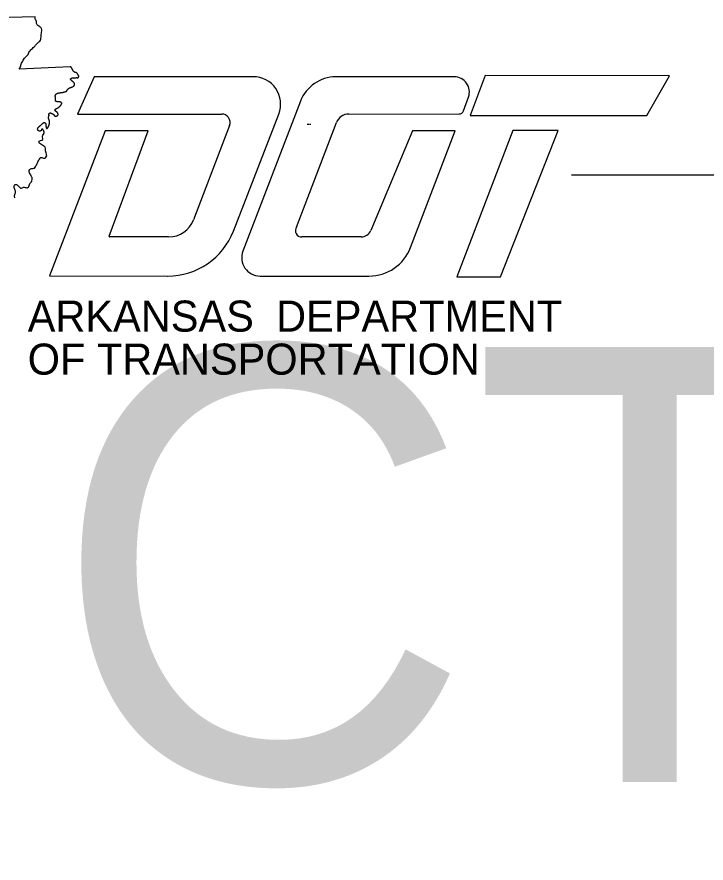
# Model space of a CAD drawing. Extents: x 840176 to 859715, y 1589036 to 1600368.
# Drawn here: x 848478 to 848941, y 1598648 to 1599216 of the extents above; entities that cross this region are included whole.
import ezdxf

# ---------------------------------------------------------------- set-up
doc = ezdxf.new("R2010")
doc.units = 0
for name, color, linetype in [('Default', 7, 'Continuous'), ('DSN_DRFT_Border', 7, 'Continuous'), ('SHET_Border-Lines', 7, 'Continuous')]:
    doc.layers.add(name, color=color, linetype=linetype)

msp = doc.modelspace()

# ---------------------------------------------------------------- linework, layer by layer
at = {"layer": 'Default'}
msp.add_line((848850.24, 1599109.73), (849966.97, 1599109.73), dxfattribs=at)
at = {"layer": 'DSN_DRFT_Border'}
for p, q in [((848672.92, 1599143.76), (848674, 1599143.76)), ((848674.34, 1599143.76), (848675.42, 1599143.76))]:
    msp.add_line(p, q, dxfattribs=at)
msp.add_lwpolyline([(848674.14, 1599143.71), (848674.14, 1599143.72), (848674.13, 1599143.73), (848674.13, 1599143.78), (848674.13, 1599143.81), (848674.23, 1599143.81), (848674.23, 1599143.8), (848674.23, 1599143.8), (848674.24, 1599143.8), (848674.21, 1599143.74), (848674.21, 1599143.71)], close=True, dxfattribs=at)
at = {"layer": 'SHET_Border-Lines'}
for p, q in [((848513.7, 1599182.3), (848479.52, 1599180.58)), ((848529.83, 1599175.52), (848518.6, 1599150.52)), ((848636.63, 1599175.57), (848529.83, 1599175.52)), ((848771.6, 1599175.51), (848692.13, 1599175.48)), ((848792.38, 1599176.27), (848782.17, 1599149.5)), ((848916.08, 1599176.05), (848792.38, 1599176.27)), ((848900.8, 1599149.5), (848916.08, 1599176.05)), ((848777.76, 1599152.59), (848781.14, 1599161.88)), ((848668.35, 1599159.13), (848629.76, 1599058.46)), ((848518.6, 1599150.52), (848615.49, 1599150.51)), ((848623.35, 1599071.94), (848653.81, 1599150.5)), ((848700.8, 1599150.51), (848774.82, 1599150.53)), ((848782.17, 1599149.5), (848900.8, 1599149.5)), ((848665.67, 1599074.61), (848692.5, 1599144.8)), ((848566.11, 1599139.27), (848537.36, 1599139.28)), ((848539.88, 1599068.57), (848566.11, 1599139.27)), ((848620.75, 1599142.89), (848596.65, 1599079.57)), ((848743.56, 1599139.3), (848715.57, 1599072.3)), ((848742.25, 1599060.88), (848772.29, 1599139.22)), ((848772.29, 1599139.22), (848743.56, 1599139.3)), ((848811.01, 1599139.45), (848773.36, 1599041.27)), ((848802.56, 1599041.27), (848841.41, 1599139.45)), ((848841.41, 1599139.45), (848811.01, 1599139.45)), ((848579.87, 1599068), (848540.28, 1599067.99)), ((848709.1, 1599067.99), (848669.26, 1599067.95)), ((848641.26, 1599041.72), (848714.34, 1599041.7)), ((848773.36, 1599041.27), (848802.56, 1599041.27))]:
    msp.add_line(p, q, dxfattribs=at)
for points in [[(848490.35, 1599215.71), (848455.4, 1599214.89), (848380.06, 1599213.74), (848316.15, 1599213.61), (848243.39, 1599213.66)], [(848537.36, 1599139.28), (848499.85, 1599041.81), (848579.21, 1599041.74)]]:
    msp.add_lwpolyline(points, dxfattribs=at)
for centre, radius, start, end in [((848636.64, 1599157.15), 18.41, 338.81, 90.0244), ((848692.14, 1599150.01), 25.47, 90.0159, 159.0252), ((848771.61, 1599165.36), 10.15, 339.9797, 90.0159), ((848615.49, 1599144.89), 5.63, 339.1692, 89.9954), ((848700.8, 1599141.63), 8.88, 90.0183, 159.0781), ((848774.82, 1599153.67), 3.13, 270.0183, 339.9797), ((848579.87, 1599085.95), 17.95, 270.0081, 339.1692), ((848579.25, 1599089.03), 47.3, 269.9471, 338.81), ((848669.24, 1599072.24), 4.29, 146.4856, 270.228), ((848709.09, 1599075.01), 7.02, 270.0618, 337.3322), ((848540.28, 1599068.42), 0.424, 159.6445, 270.0081), ((848641.26, 1599054.05), 12.32, 159.0252, 269.9823), ((848714.35, 1599071.58), 29.88, 269.9823, 339.0187)]:
    msp.add_arc(centre, radius, start, end, dxfattribs=at)
for points in [[(848479.52, 1599180.58), (848480.73, 1599183.32), (848480.98, 1599184.67), (848482.01, 1599186.03), (848482.54, 1599187.28), (848483.64, 1599188.49), (848484.46, 1599189.38), (848485.46, 1599190.38), (848485.95, 1599191.76), (848486.87, 1599193.01), (848487.81, 1599194.01), (848488.96, 1599195.14), (848490.17, 1599196.21), (848490.83, 1599197.24), (848491.78, 1599198.18), (848492.8, 1599198.98), (848493.9, 1599200.1), (848494.16, 1599201.51), (848494.34, 1599203.04), (848494.41, 1599204.78), (848494.77, 1599206.34), (848494.52, 1599207.88), (848493.36, 1599209.21), (848492.06, 1599210), (848491.29, 1599210.82), (848491.19, 1599212.71), (848490.58, 1599213.74), (848490.35, 1599215.71)], [(848488.7, 1599114.01), (848489.78, 1599114.22), (848490.78, 1599115.57), (848491.27, 1599116.73), (848491.78, 1599117.8), (848492.44, 1599119.08), (848493.11, 1599120.31), (848494.06, 1599121.23), (848495.23, 1599121.15), (848496.26, 1599120.82), (848497.2, 1599121.1), (848497.99, 1599122.43), (848497.82, 1599123.58), (848497.38, 1599125.17), (848497.15, 1599126.37), (848496.89, 1599128.19), (848496.05, 1599128.98), (848494.69, 1599129.72), (848493.36, 1599130.74), (848492.62, 1599131.79), (848493.9, 1599132.71), (848495.33, 1599133.48), (848495.18, 1599134.89), (848495.46, 1599136.27), (848496.26, 1599137.68), (848496.08, 1599138.96)], [(848476.5, 1599094.34), (848476.66, 1599096.44), (848477.07, 1599097.67), (848476.63, 1599099.74), (848476.2, 1599101.27), (848476.38, 1599102.76), (848477.32, 1599103.24), (848478.24, 1599102.94), (848479.04, 1599102.12), (848480.01, 1599101.07), (848480.96, 1599100.74), (848481.93, 1599101.25), (848482.93, 1599101.32), (848484.08, 1599101.12), (848485.15, 1599101.02), (848485.71, 1599101.38), (848486.28, 1599102.45), (848486.66, 1599103.88), (848487.45, 1599104.57), (848488.07, 1599105.7), (848488.32, 1599107.21), (848487.86, 1599108.44), (848487.22, 1599109.82), (848486.41, 1599110.97), (848486.28, 1599112.63), (848487.12, 1599113.63), (848488.58, 1599113.99), (848488.7, 1599114.01)]]:
    msp.add_spline(points, degree=3, dxfattribs=at)
for points in [[(848516.17, 1599174.7), (848516.28, 1599174.69), (848516.39, 1599174.68), (848516.49, 1599174.7), (848516.72, 1599174.73), (848516.95, 1599174.77), (848517.18, 1599174.81), (848517.41, 1599174.85), (848517.64, 1599174.89), (848517.87, 1599174.93), (848517.93, 1599174.94), (848517.98, 1599174.94), (848518.03, 1599174.94), (848518.09, 1599174.94), (848518.14, 1599174.94), (848518.19, 1599174.93), (848518.3, 1599174.93), (848518.41, 1599174.91), (848518.51, 1599174.9), (848518.62, 1599174.9), (848518.73, 1599174.9), (848518.83, 1599174.91), (848518.95, 1599174.93), (848519.05, 1599174.97), (848519.15, 1599175.03), (848519.17, 1599175.04), (848519.19, 1599175.06), (848519.21, 1599175.07), (848519.23, 1599175.09), (848519.25, 1599175.1), (848519.27, 1599175.12), (848519.3, 1599175.15), (848519.33, 1599175.19), (848519.35, 1599175.23), (848519.41, 1599175.3), (848519.44, 1599175.39), (848519.47, 1599175.48), (848519.49, 1599175.57), (848519.5, 1599175.66), (848519.5, 1599175.75), (848519.5, 1599175.83), (848519.49, 1599175.92), (848519.46, 1599176), (848519.33, 1599176.42), (848519.13, 1599176.78), (848518.9, 1599177.15), (848518.65, 1599177.54), (848518.39, 1599177.89), (848518.03, 1599178.18), (848517.94, 1599178.24), (848517.86, 1599178.29), (848517.76, 1599178.31), (848517.66, 1599178.34), (848517.56, 1599178.36), (848517.46, 1599178.38), (848517.36, 1599178.41), (848517.26, 1599178.42), (848517.16, 1599178.45), (848517.06, 1599178.47), (848516.97, 1599178.51), (848516.88, 1599178.56), (848516.51, 1599178.76), (848516.19, 1599179), (848515.93, 1599179.33), (848515.85, 1599179.43), (848515.78, 1599179.54), (848515.72, 1599179.65), (848515.67, 1599179.77), (848515.61, 1599179.88), (848515.56, 1599180), (848515.51, 1599180.11), (848515.46, 1599180.23), (848515.4, 1599180.35), (848515.35, 1599180.46), (848515.28, 1599180.57), (848515.21, 1599180.68), (848515.16, 1599180.77), (848515.11, 1599180.85), (848515.06, 1599180.93), (848515, 1599181.01), (848514.95, 1599181.1), (848514.9, 1599181.18), (848514.8, 1599181.35), (848514.69, 1599181.52), (848514.57, 1599181.69), (848514.47, 1599181.84), (848514.35, 1599181.97), (848514.19, 1599182.09), (848514.04, 1599182.2), (848513.88, 1599182.27), (848513.7, 1599182.3)], [(848512.12, 1599167.1), (848512.14, 1599167.13), (848512.17, 1599167.15), (848512.19, 1599167.18), (848512.28, 1599167.28), (848512.38, 1599167.38), (848512.48, 1599167.48), (848512.57, 1599167.58), (848512.68, 1599167.67), (848512.79, 1599167.75), (848512.9, 1599167.84), (848513.01, 1599167.91), (848513.14, 1599167.97), (848513.26, 1599168.02), (848513.37, 1599168.07), (848513.49, 1599168.11), (848513.61, 1599168.16), (848513.73, 1599168.2), (848513.85, 1599168.24), (848513.97, 1599168.28), (848514.1, 1599168.31), (848514.22, 1599168.35), (848514.34, 1599168.39), (848514.45, 1599168.44), (848514.57, 1599168.48), (848514.81, 1599168.57), (848515.05, 1599168.66), (848515.28, 1599168.76), (848515.53, 1599168.86), (848515.75, 1599168.98), (848515.98, 1599169.12), (848516.09, 1599169.19), (848516.17, 1599169.27), (848516.26, 1599169.36), (848516.35, 1599169.45), (848516.41, 1599169.54), (848516.48, 1599169.65), (848516.59, 1599169.86), (848516.68, 1599170.07), (848516.72, 1599170.3), (848516.74, 1599170.4), (848516.75, 1599170.5), (848516.74, 1599170.6), (848516.73, 1599170.71), (848516.71, 1599170.82), (848516.68, 1599170.93), (848516.65, 1599171.04), (848516.61, 1599171.14), (848516.56, 1599171.24), (848516.5, 1599171.34), (848516.44, 1599171.44), (848516.36, 1599171.52), (848516.27, 1599171.64), (848516.16, 1599171.74), (848516.05, 1599171.84), (848515.94, 1599171.93), (848515.83, 1599172.02), (848515.72, 1599172.1), (848515.61, 1599172.19), (848515.49, 1599172.27), (848515.38, 1599172.36), (848515.27, 1599172.45), (848515.17, 1599172.55), (848515.06, 1599172.65), (848514.85, 1599172.84), (848514.65, 1599173.04), (848514.45, 1599173.25), (848514.35, 1599173.34), (848514.27, 1599173.44), (848514.2, 1599173.55), (848514.13, 1599173.65), (848514.09, 1599173.74), (848514.06, 1599173.85), (848514.06, 1599173.87), (848514.06, 1599173.9), (848514.06, 1599173.92), (848514.06, 1599173.94), (848514.06, 1599173.96), (848514.07, 1599173.99), (848514.08, 1599174.03), (848514.11, 1599174.08), (848514.14, 1599174.12), (848514.22, 1599174.22), (848514.3, 1599174.3), (848514.41, 1599174.37), (848514.53, 1599174.45), (848514.65, 1599174.52), (848514.78, 1599174.59), (848514.91, 1599174.65), (848515.03, 1599174.7), (848515.16, 1599174.75), (848515.22, 1599174.77), (848515.27, 1599174.78), (848515.33, 1599174.79), (848515.38, 1599174.8), (848515.44, 1599174.8), (848515.49, 1599174.8), (848515.61, 1599174.79), (848515.72, 1599174.78), (848515.83, 1599174.76), (848515.94, 1599174.74), (848516.05, 1599174.72), (848516.16, 1599174.7), (848516.17, 1599174.7), (848516.17, 1599174.7), (848516.17, 1599174.7)], [(848503.8, 1599159.91), (848503.8, 1599160), (848503.81, 1599160.1), (848503.83, 1599160.19), (848503.85, 1599160.34), (848503.9, 1599160.48), (848503.92, 1599160.63), (848503.94, 1599160.77), (848503.96, 1599160.92), (848503.96, 1599161.06), (848503.95, 1599161.2), (848503.93, 1599161.34), (848503.91, 1599161.48), (848503.89, 1599161.62), (848503.87, 1599161.75), (848503.85, 1599161.89), (848503.83, 1599162.03), (848503.81, 1599162.17), (848503.8, 1599162.31), (848503.78, 1599162.45), (848503.78, 1599162.59), (848503.78, 1599162.72), (848503.78, 1599162.83), (848503.79, 1599162.94), (848503.82, 1599163.04), (848503.84, 1599163.15), (848503.88, 1599163.25), (848503.93, 1599163.35), (848504.05, 1599163.56), (848504.19, 1599163.74), (848504.37, 1599163.9), (848504.42, 1599163.95), (848504.47, 1599164), (848504.53, 1599164.04), (848504.59, 1599164.08), (848504.65, 1599164.13), (848504.7, 1599164.16), (848504.82, 1599164.24), (848504.93, 1599164.3), (848505.05, 1599164.36), (848505.17, 1599164.41), (848505.29, 1599164.46), (848505.42, 1599164.49), (848505.54, 1599164.53), (848505.67, 1599164.56), (848505.8, 1599164.59), (848506.03, 1599164.64), (848506.26, 1599164.69), (848506.5, 1599164.73), (848506.73, 1599164.78), (848506.97, 1599164.82), (848507.2, 1599164.85), (848507.31, 1599164.86), (848507.42, 1599164.87), (848507.53, 1599164.88), (848507.63, 1599164.89), (848507.74, 1599164.89), (848507.85, 1599164.9), (848507.95, 1599164.91), (848508.06, 1599164.91), (848508.17, 1599164.92), (848508.27, 1599164.93), (848508.38, 1599164.95), (848508.48, 1599164.98), (848508.73, 1599165.03), (848508.97, 1599165.09), (848509.2, 1599165.17), (848509.44, 1599165.24), (848509.68, 1599165.31), (848509.92, 1599165.38), (848510.15, 1599165.45), (848510.38, 1599165.52), (848510.61, 1599165.59), (848510.85, 1599165.66), (848511.07, 1599165.74), (848511.3, 1599165.84), (848511.39, 1599165.88), (848511.46, 1599165.95), (848511.51, 1599166.03), (848511.57, 1599166.12), (848511.6, 1599166.21), (848511.64, 1599166.31), (848511.68, 1599166.41), (848511.71, 1599166.51), (848511.76, 1599166.61), (848511.8, 1599166.7), (848511.85, 1599166.79), (848511.91, 1599166.87), (848511.98, 1599166.95), (848512.05, 1599167.03), (848512.12, 1599167.1)], [(848504.03, 1599152.32), (848504, 1599152.34), (848503.98, 1599152.37), (848503.96, 1599152.39), (848503.81, 1599152.52), (848503.71, 1599152.68), (848503.62, 1599152.86), (848503.55, 1599153), (848503.52, 1599153.2), (848503.6, 1599153.33), (848503.65, 1599153.43), (848503.72, 1599153.52), (848503.8, 1599153.6), (848503.88, 1599153.69), (848503.96, 1599153.77), (848504.06, 1599153.85), (848504.25, 1599154.01), (848504.45, 1599154.16), (848504.67, 1599154.28), (848504.76, 1599154.33), (848504.86, 1599154.38), (848504.96, 1599154.41), (848505.05, 1599154.45), (848505.15, 1599154.48), (848505.25, 1599154.52), (848505.34, 1599154.55), (848505.44, 1599154.58), (848505.53, 1599154.62), (848505.63, 1599154.66), (848505.72, 1599154.71), (848505.8, 1599154.77), (848506.2, 1599155.07), (848506.56, 1599155.4), (848506.9, 1599155.77), (848506.99, 1599155.86), (848507.08, 1599155.96), (848507.16, 1599156.06), (848507.24, 1599156.16), (848507.32, 1599156.26), (848507.4, 1599156.36), (848507.56, 1599156.57), (848507.7, 1599156.78), (848507.84, 1599156.99), (848507.95, 1599157.15), (848508.02, 1599157.32), (848508.08, 1599157.49), (848508.11, 1599157.58), (848508.11, 1599157.67), (848508.1, 1599157.76), (848508.08, 1599157.84), (848508.05, 1599157.92), (848508, 1599157.99), (848507.96, 1599158.04), (848507.92, 1599158.09), (848507.87, 1599158.13), (848507.82, 1599158.17), (848507.78, 1599158.22), (848507.73, 1599158.25), (848507.63, 1599158.33), (848507.53, 1599158.39), (848507.42, 1599158.45), (848507.19, 1599158.56), (848506.96, 1599158.64), (848506.72, 1599158.68), (848506.61, 1599158.7), (848506.5, 1599158.72), (848506.39, 1599158.72), (848506.28, 1599158.72), (848506.18, 1599158.72), (848506.07, 1599158.71), (848505.96, 1599158.71), (848505.85, 1599158.71), (848505.74, 1599158.71), (848505.63, 1599158.7), (848505.52, 1599158.72), (848505.41, 1599158.73), (848505.28, 1599158.75), (848505.14, 1599158.77), (848505, 1599158.79), (848504.87, 1599158.81), (848504.73, 1599158.84), (848504.59, 1599158.86), (848504.46, 1599158.89), (848504.34, 1599158.94), (848504.22, 1599159.02), (848504.1, 1599159.1), (848504, 1599159.2), (848503.93, 1599159.32), (848503.91, 1599159.36), (848503.89, 1599159.39), (848503.87, 1599159.43), (848503.86, 1599159.46), (848503.85, 1599159.5), (848503.84, 1599159.54), (848503.81, 1599159.61), (848503.8, 1599159.68), (848503.8, 1599159.75), (848503.79, 1599159.81), (848503.79, 1599159.86), (848503.8, 1599159.91)], [(848499.2, 1599148.17), (848499.2, 1599148.22), (848499.21, 1599148.27), (848499.22, 1599148.31), (848499.25, 1599148.43), (848499.28, 1599148.55), (848499.33, 1599148.66), (848499.38, 1599148.78), (848499.43, 1599148.9), (848499.48, 1599149.02), (848499.52, 1599149.13), (848499.56, 1599149.25), (848499.58, 1599149.37), (848499.59, 1599149.42), (848499.59, 1599149.47), (848499.59, 1599149.53), (848499.58, 1599149.58), (848499.58, 1599149.63), (848499.57, 1599149.68), (848499.55, 1599149.79), (848499.52, 1599149.9), (848499.5, 1599150.01), (848499.47, 1599150.11), (848499.46, 1599150.22), (848499.47, 1599150.33), (848499.47, 1599150.44), (848499.52, 1599150.55), (848499.58, 1599150.65), (848499.61, 1599150.7), (848499.65, 1599150.74), (848499.68, 1599150.79), (848499.72, 1599150.83), (848499.76, 1599150.87), (848499.79, 1599150.92), (848499.87, 1599151), (848499.95, 1599151.06), (848500.04, 1599151.13), (848500.11, 1599151.19), (848500.2, 1599151.23), (848500.29, 1599151.25), (848500.38, 1599151.27), (848500.47, 1599151.27), (848500.55, 1599151.24), (848500.85, 1599151.12), (848501.13, 1599150.97), (848501.42, 1599150.85), (848501.74, 1599150.72), (848502.07, 1599150.61), (848502.4, 1599150.47), (848502.5, 1599150.42), (848502.59, 1599150.35), (848502.65, 1599150.25), (848502.71, 1599150.15), (848502.77, 1599150.04), (848502.83, 1599149.94), (848502.88, 1599149.83), (848502.94, 1599149.72), (848503, 1599149.61), (848503.05, 1599149.5), (848503.14, 1599149.42), (848503.24, 1599149.34), (848503.42, 1599149.21), (848503.62, 1599149.15), (848503.83, 1599149.11), (848504.03, 1599149.07), (848504.24, 1599149.07), (848504.44, 1599149.11), (848504.64, 1599149.16), (848504.83, 1599149.23), (848505.01, 1599149.34), (848505.11, 1599149.39), (848505.2, 1599149.45), (848505.28, 1599149.53), (848505.32, 1599149.56), (848505.36, 1599149.6), (848505.4, 1599149.64), (848505.44, 1599149.69), (848505.48, 1599149.73), (848505.52, 1599149.78), (848505.71, 1599150.04), (848505.71, 1599150.44), (848505.59, 1599150.73), (848505.45, 1599151.1), (848505.23, 1599151.45), (848504.93, 1599151.75), (848504.86, 1599151.82), (848504.79, 1599151.88), (848504.7, 1599151.93), (848504.62, 1599151.98), (848504.53, 1599152.02), (848504.45, 1599152.07), (848504.36, 1599152.12), (848504.27, 1599152.16), (848504.19, 1599152.21), (848504.13, 1599152.24), (848504.08, 1599152.28), (848504.03, 1599152.32)], [(848496.08, 1599138.96), (848495.99, 1599139.21), (848495.9, 1599139.47), (848495.77, 1599139.7), (848495.71, 1599139.82), (848495.65, 1599139.94), (848495.57, 1599140.05), (848495.54, 1599140.1), (848495.5, 1599140.16), (848495.46, 1599140.21), (848495.42, 1599140.26), (848495.38, 1599140.31), (848495.33, 1599140.36), (848495.29, 1599140.41), (848495.23, 1599140.44), (848495.17, 1599140.45), (848495.1, 1599140.46), (848495.02, 1599140.46), (848494.95, 1599140.44), (848494.88, 1599140.42), (848494.81, 1599140.39), (848494.74, 1599140.36), (848494.67, 1599140.32), (848494.62, 1599140.29), (848494.57, 1599140.24), (848494.51, 1599140.18), (848494.47, 1599140.11), (848494.45, 1599140.03), (848494.43, 1599139.94), (848494.42, 1599139.86), (848494.4, 1599139.77), (848494.39, 1599139.69), (848494.37, 1599139.6), (848494.34, 1599139.52), (848494.32, 1599139.43), (848494.25, 1599139.37), (848494.18, 1599139.32), (848494.12, 1599139.27), (848494.06, 1599139.23), (848493.99, 1599139.2), (848493.93, 1599139.17), (848493.87, 1599139.14), (848493.8, 1599139.11), (848493.74, 1599139.09), (848493.67, 1599139.07), (848493.61, 1599139.06), (848493.54, 1599139.04), (848493.48, 1599139.04), (848493.42, 1599139.03), (848493.33, 1599139.03), (848493.25, 1599139.04), (848493.17, 1599139.05), (848493.08, 1599139.05), (848493, 1599139.07), (848492.92, 1599139.1), (848492.83, 1599139.12), (848492.75, 1599139.16), (848492.67, 1599139.21), (848492.58, 1599139.26), (848492.49, 1599139.32), (848492.42, 1599139.39), (848492.39, 1599139.42), (848492.36, 1599139.44), (848492.33, 1599139.47), (848492.31, 1599139.5), (848492.28, 1599139.53), (848492.26, 1599139.56), (848492.21, 1599139.61), (848492.17, 1599139.67), (848492.13, 1599139.73), (848492.05, 1599139.84), (848492, 1599139.96), (848491.96, 1599140.1), (848491.92, 1599140.22), (848491.9, 1599140.34), (848491.91, 1599140.46), (848491.92, 1599140.57), (848491.94, 1599140.69), (848491.98, 1599140.8), (848492.03, 1599140.91), (848492.07, 1599141), (848492.13, 1599141.1), (848492.19, 1599141.2), (848492.24, 1599141.3), (848492.31, 1599141.4), (848492.45, 1599141.6), (848492.6, 1599141.79), (848492.78, 1599141.95), (848492.88, 1599142.05), (848492.99, 1599142.14), (848493.1, 1599142.23), (848493.21, 1599142.32), (848493.32, 1599142.41), (848493.43, 1599142.5), (848493.54, 1599142.59), (848493.65, 1599142.68), (848493.76, 1599142.77), (848493.87, 1599142.86), (848493.98, 1599142.95), (848494.08, 1599143.05), (848494.26, 1599143.22), (848494.43, 1599143.39), (848494.6, 1599143.56), (848494.78, 1599143.73), (848494.95, 1599143.9), (848495.13, 1599144.07), (848495.27, 1599144.21), (848495.42, 1599144.33), (848495.58, 1599144.45), (848495.65, 1599144.51), (848495.73, 1599144.57), (848495.81, 1599144.63), (848495.89, 1599144.68), (848495.97, 1599144.74), (848496.05, 1599144.79), (848496.14, 1599144.84), (848496.24, 1599144.87), (848496.34, 1599144.87)], [(848496.34, 1599144.87), (848496.37, 1599144.87), (848496.39, 1599144.87), (848496.42, 1599144.87), (848496.55, 1599144.85), (848496.68, 1599144.8), (848496.79, 1599144.71), (848496.87, 1599144.66), (848496.93, 1599144.6), (848496.98, 1599144.53), (848497.04, 1599144.47), (848497.09, 1599144.41), (848497.14, 1599144.34), (848497.19, 1599144.27), (848497.23, 1599144.2), (848497.26, 1599144.13), (848497.29, 1599144.05), (848497.32, 1599143.97), (848497.33, 1599143.89), (848497.35, 1599143.78), (848497.37, 1599143.67), (848497.38, 1599143.55), (848497.4, 1599143.43), (848497.41, 1599143.32), (848497.42, 1599143.2), (848497.45, 1599142.97), (848497.48, 1599142.74), (848497.51, 1599142.51), (848497.55, 1599142.22), (848497.6, 1599141.93), (848497.66, 1599141.64), (848497.71, 1599141.36), (848497.78, 1599141.08), (848497.87, 1599140.8), (848497.88, 1599140.77), (848497.9, 1599140.74), (848497.93, 1599140.72), (848497.96, 1599140.69), (848497.99, 1599140.69), (848498.02, 1599140.7), (848498.11, 1599140.72), (848498.2, 1599140.75), (848498.28, 1599140.81), (848498.48, 1599140.95), (848498.64, 1599141.09), (848498.76, 1599141.29), (848498.84, 1599141.41), (848498.92, 1599141.54), (848498.99, 1599141.67), (848499.06, 1599141.8), (848499.13, 1599141.93), (848499.2, 1599142.06), (848499.27, 1599142.19), (848499.33, 1599142.32), (848499.38, 1599142.46), (848499.44, 1599142.59), (848499.49, 1599142.73), (848499.53, 1599142.87), (848499.69, 1599143.38), (848499.8, 1599143.91), (848499.89, 1599144.43), (848499.95, 1599144.79), (848500, 1599145.16), (848499.91, 1599145.51), (848499.8, 1599145.98), (848499.66, 1599146.45), (848499.53, 1599146.91), (848499.43, 1599147.26), (848499.32, 1599147.61), (848499.22, 1599147.96), (848499.2, 1599148.03), (848499.2, 1599148.1), (848499.2, 1599148.17)]]:
    msp.add_open_spline(points, degree=3, dxfattribs=at)

# ---------------------------------------------------------------- texts
at = {"layer": 'Default'}
msp.add_text('DISTRICTS 5, 8 & 9', height=292.2095, dxfattribs=at).set_placement((847220.58, 1598701.93))
at = {"layer": 'SHET_Border-Lines'}
for s, height, p in [('ARKANSAS', 20.846, (848485.25, 1599004.41)), ('DEPARTMENT', 20.846, (848652, 1599004.41)), ('OF TRANSPORTATION', 20.8462, (848485.25, 1598975.54))]:
    msp.add_text(s, height=height, dxfattribs=at).set_placement(p)

doc.saveas('drawing.dxf')
